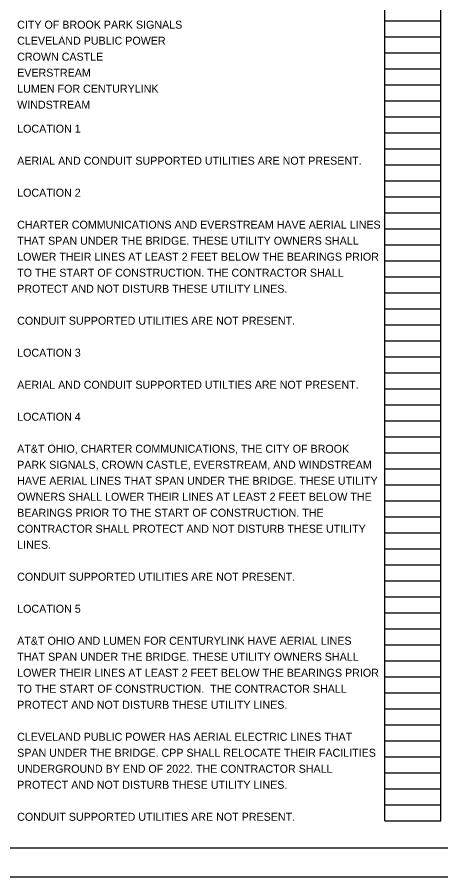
# Model space of a CAD drawing. Extents: x 0 to 34, y -14.6 to 28.2.
# Drawn here: x 17.24 to 24.66, y 0 to 15.04 of the extents above; entities that cross this region are included whole.
import ezdxf

# ---------------------------------------------------------------- set-up
doc = ezdxf.new("R2010")
doc.units = 0
for name, color, linetype in [('SH_Border', 7, 'Continuous'), ('SH_Cut_Line', 7, 'Continuous'), ('SH_Data', 7, 'Continuous'), ('SH_Text', 7, 'Continuous')]:
    doc.layers.add(name, color=color, linetype=linetype)

msp = doc.modelspace()

# ---------------------------------------------------------------- linework, layer by layer
at = {"layer": 'SH_Border'}
msp.add_lwpolyline([(1.5, 21.5), (33.5, 21.5), (33.5, 0.5), (1.5, 0.5)], close=True, dxfattribs=at)
at = {"layer": 'SH_Cut_Line'}
msp.add_lwpolyline([(0, 0), (34, 0), (34, 22), (0, 22)], close=True, dxfattribs=at)
at = {"layer": 'SH_Data'}
for p, q in [((23.68, 0.98), (23.68, 21.14)), ((24.66, 0.98), (24.66, 21.14)), ((23.68, 14.98), (24.66, 14.98)), ((23.68, 14.7), (24.66, 14.7)), ((23.68, 14.42), (24.66, 14.42)), ((23.68, 14.14), (24.66, 14.14)), ((23.68, 13.86), (24.66, 13.86)), ((23.68, 13.58), (24.66, 13.58)), ((23.68, 13.3), (24.66, 13.3)), ((23.68, 13.02), (24.66, 13.02)), ((23.68, 12.74), (24.66, 12.74)), ((23.68, 12.46), (24.66, 12.46)), ((23.68, 12.18), (24.66, 12.18)), ((23.68, 11.9), (24.66, 11.9)), ((23.68, 11.62), (24.66, 11.62)), ((23.68, 11.34), (24.66, 11.34)), ((23.68, 11.06), (24.66, 11.06)), ((23.68, 10.78), (24.66, 10.78)), ((23.68, 10.5), (24.66, 10.5)), ((23.68, 10.22), (24.66, 10.22)), ((23.68, 9.94), (24.66, 9.94)), ((23.68, 9.66), (24.66, 9.66)), ((23.68, 9.38), (24.66, 9.38)), ((23.68, 9.1), (24.66, 9.1)), ((23.68, 8.82), (24.66, 8.82)), ((23.68, 8.54), (24.66, 8.54)), ((23.68, 8.26), (24.66, 8.26)), ((23.68, 7.98), (24.66, 7.98)), ((23.68, 7.7), (24.66, 7.7)), ((23.68, 7.42), (24.66, 7.42)), ((23.68, 7.14), (24.66, 7.14)), ((23.68, 6.86), (24.66, 6.86)), ((23.68, 6.58), (24.66, 6.58)), ((23.68, 6.3), (24.66, 6.3)), ((23.68, 6.02), (24.66, 6.02)), ((23.68, 5.74), (24.66, 5.74)), ((23.68, 5.46), (24.66, 5.46)), ((23.68, 5.18), (24.66, 5.18)), ((23.68, 4.9), (24.66, 4.9)), ((23.68, 4.62), (24.66, 4.62)), ((23.68, 4.34), (24.66, 4.34)), ((23.68, 4.06), (24.66, 4.06)), ((23.68, 3.78), (24.66, 3.78)), ((23.68, 3.5), (24.66, 3.5)), ((23.68, 3.22), (24.66, 3.22)), ((23.68, 2.94), (24.66, 2.94)), ((23.68, 2.66), (24.66, 2.66)), ((23.68, 2.38), (24.66, 2.38)), ((23.68, 2.1), (24.66, 2.1)), ((23.68, 1.82), (24.66, 1.82)), ((23.68, 1.54), (24.66, 1.54)), ((23.68, 1.26), (24.66, 1.26)), ((23.68, 0.98), (24.66, 0.98))]:
    msp.add_line(p, q, dxfattribs=at)

# ---------------------------------------------------------------- texts
at = {"layer": 'SH_Text'}
for s, p in [('CITY OF BROOK PARK SIGNALS', (17.24, 14.84)), ('CLEVELAND PUBLIC POWER', (17.24, 14.56)), ('CROWN CASTLE', (17.24, 14.28)), ('EVERSTREAM', (17.24, 14)), ('LUMEN FOR CENTURYLINK', (17.24, 13.72)), ('WINDSTREAM', (17.24, 13.44)), ('LOCATION 1', (17.24, 13.02)), ('AERIAL AND CONDUIT SUPPORTED UTILITIES ARE NOT PRESENT.', (17.24, 12.46)), ('LOCATION 2', (17.24, 11.9)), ('CHARTER COMMUNICATIONS AND EVERSTREAM HAVE AERIAL LINES ', (17.24, 11.34)), ('THAT SPAN UNDER THE BRIDGE. THESE UTILITY OWNERS SHALL ', (17.24, 11.06)), ('LOWER THEIR LINES AT LEAST 2 FEET BELOW THE BEARINGS PRIOR ', (17.24, 10.78)), ('TO THE START OF CONSTRUCTION. THE CONTRACTOR SHALL ', (17.24, 10.5)), ('PROTECT AND NOT DISTURB THESE UTILITY LINES.', (17.24, 10.22)), ('CONDUIT SUPPORTED UTILITIES ARE NOT PRESENT.', (17.24, 9.66)), ('LOCATION 3', (17.24, 9.1)), ('AERIAL AND CONDUIT SUPPORTED UTILTIES ARE NOT PRESENT.', (17.24, 8.54)), ('LOCATION 4', (17.24, 7.98)), ('AT&T OHIO, CHARTER COMMUNICATIONS, THE CITY OF BROOK ', (17.24, 7.42)), ('PARK SIGNALS, CROWN CASTLE, EVERSTREAM, AND WINDSTREAM ', (17.24, 7.14)), ('HAVE AERIAL LINES THAT SPAN UNDER THE BRIDGE. THESE UTILITY ', (17.24, 6.86)), ('OWNERS SHALL LOWER THEIR LINES AT LEAST 2 FEET BELOW THE ', (17.24, 6.58)), ('BEARINGS PRIOR TO THE START OF CONSTRUCTION. THE ', (17.24, 6.3)), ('CONTRACTOR SHALL PROTECT AND NOT DISTURB THESE UTILITY ', (17.24, 6.02)), ('LINES.', (17.24, 5.74)), ('CONDUIT SUPPORTED UTILITIES ARE NOT PRESENT.', (17.24, 5.18)), ('LOCATION 5', (17.24, 4.62)), ('AT&T OHIO AND LUMEN FOR CENTURYLINK HAVE AERIAL LINES ', (17.24, 4.06)), ('THAT SPAN UNDER THE BRIDGE. THESE UTILITY OWNERS SHALL ', (17.24, 3.78)), ('LOWER THEIR LINES AT LEAST 2 FEET BELOW THE BEARINGS PRIOR ', (17.24, 3.5)), ('TO THE START OF CONSTRUCTION.  THE CONTRACTOR SHALL ', (17.24, 3.22)), ('PROTECT AND NOT DISTURB THESE UTILITY LINES.', (17.24, 2.94)), ('CLEVELAND PUBLIC POWER HAS AERIAL ELECTRIC LINES THAT ', (17.24, 2.38)), ('SPAN UNDER THE BRIDGE. CPP SHALL RELOCATE THEIR FACILITIES ', (17.24, 2.1)), ('UNDERGROUND BY END OF 2022. THE CONTRACTOR SHALL ', (17.24, 1.82)), ('PROTECT AND NOT DISTURB THESE UTILITY LINES.', (17.24, 1.54)), ('CONDUIT SUPPORTED UTILITIES ARE NOT PRESENT.', (17.24, 0.98))]:
    msp.add_text(s, height=0.14, dxfattribs=at).set_placement(p)

doc.saveas('drawing.dxf')
